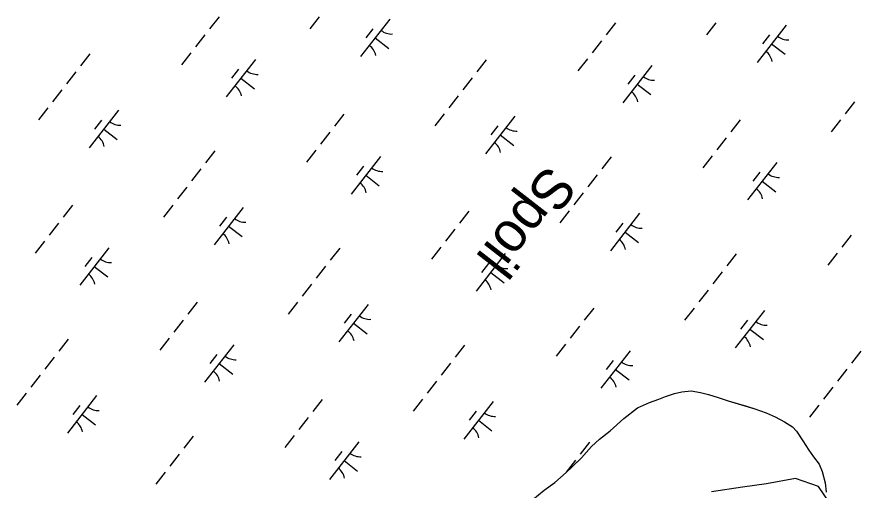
# Model space of a CAD drawing. Extents: x 3888273 to 3909528, y 158682 to 181032.
# Drawn here: x 3900589 to 3901471, y 173553 to 174052 of the extents above; entities that cross this region are included whole.
import ezdxf

# ---------------------------------------------------------------- set-up
doc = ezdxf.new("R2010")
doc.units = 0
for name, color, linetype in [('V-CHAN-SPOL', 7, 'Continuous'), ('V-RIVR-EDGE', 7, 'Continuous'), ('V-TOPO-SHOR', 7, 'Continuous'), ('V-WETL-SWMP', 7, 'Continuous')]:
    doc.layers.add(name, color=color, linetype=linetype)

msp = doc.modelspace()

# ---------------------------------------------------------------- linework, layer by layer
at = {"layer": 'V-RIVR-EDGE'}
msp.add_lwpolyline([(3901444.18, 173539.89), (3901432.1, 173557.55), (3901407.94, 173565.91), (3901377.27, 173560.34), (3901352.18, 173556.62), (3901319.66, 173551.97)], dxfattribs=at)
at = {"layer": 'V-TOPO-SHOR'}
for points in [[(3901131.66, 173543.88), (3901143.9, 173553.57), (3901154.97, 173561.65), (3901166.81, 173572.13), (3901173.11, 173578.17), (3901182.97, 173587.43), (3901193.6, 173599.49), (3901201.89, 173607.14), (3901212.94, 173616.02), (3901227.54, 173628.92), (3901241.76, 173640.22), (3901254.45, 173645.93), (3901264.37, 173649.22), (3901271.11, 173652.08), (3901280.64, 173655.37)], [(3901280.64, 173655.37), (3901288.58, 173657.04), (3901298.14, 173657.94), (3901308.11, 173656.45), (3901316.5, 173654.15), (3901326.48, 173651.07), (3901337.27, 173647.6), (3901356.45, 173641.83), (3901365.24, 173639.13), (3901377.24, 173634.87), (3901386.44, 173630.59), (3901396.45, 173625.52), (3901404.87, 173620.03), (3901408.9, 173615.69), (3901415.78, 173605.4), (3901421.86, 173595.51), (3901426.71, 173588.79), (3901432.76, 173580.89), (3901436.03, 173573.36), (3901438.94, 173561.44), (3901440.24, 173551.5)]]:
    msp.add_lwpolyline(points, dxfattribs=at)
at = {"layer": 'V-WETL-SWMP'}
for p, q in [((3900801.93, 174051.41), (3900792.1, 174038.79)), ((3900907.39, 174051.66), (3900897.57, 174039.03)), ((3900981.53, 174049.18), (3900950.83, 174009.72)), ((3901218.59, 174045.19), (3901208.77, 174032.56)), ((3901324.06, 174045.43), (3901314.23, 174032.8)), ((3901398.2, 174042.96), (3901367.5, 174003.5)), ((3900787.19, 174032.47), (3900777.36, 174019.84)), ((3900963.78, 174038.93), (3900956.41, 174029.45)), ((3901380.44, 174032.7), (3901373.07, 174023.23)), ((3900966.18, 174029.45), (3900980.39, 174018.4)), ((3901203.86, 174026.25), (3901194.03, 174013.62)), ((3901382.85, 174023.23), (3901397.06, 174012.17)), ((3900666.22, 174012.56), (3900656.39, 173999.94)), ((3900772.45, 174013.53), (3900762.63, 174000.9)), ((3900840.29, 174006.73), (3900809.59, 173967.27)), ((3901082.88, 174006.34), (3901073.06, 173993.71)), ((3901189.12, 174007.3), (3901179.29, 173994.68)), ((3900822.54, 173996.48), (3900815.17, 173987.01)), ((3901256.96, 174000.51), (3901226.26, 173961.05)), ((3900651.48, 173993.62), (3900641.65, 173980.99)), ((3901239.2, 173990.25), (3901231.83, 173980.78)), ((3900824.94, 173987), (3900839.15, 173975.95)), ((3901068.15, 173987.4), (3901058.32, 173974.77)), ((3901241.61, 173980.78), (3901255.81, 173969.72)), ((3900636.74, 173974.68), (3900626.92, 173962.05)), ((3901053.41, 173968.45), (3901043.58, 173955.83)), ((3901470.08, 173962.23), (3901460.25, 173949.6)), ((3900622, 173955.74), (3900612.18, 173943.11)), ((3900696.15, 173953.26), (3900665.44, 173913.8)), ((3900933.21, 173949.27), (3900923.38, 173936.64)), ((3901038.67, 173949.51), (3901028.85, 173936.88)), ((3901112.81, 173947.04), (3901082.11, 173907.58)), ((3900678.39, 173943.01), (3900671.02, 173933.54)), ((3901095.06, 173936.78), (3901087.69, 173927.31)), ((3901349.88, 173943.04), (3901340.05, 173930.42)), ((3901455.34, 173943.29), (3901445.51, 173930.66)), ((3900680.79, 173933.53), (3900695, 173922.48)), ((3900918.47, 173930.33), (3900908.64, 173917.7)), ((3901097.46, 173927.31), (3901111.67, 173916.25)), ((3901335.14, 173924.1), (3901325.31, 173911.47)), ((3900797.5, 173910.42), (3900787.67, 173897.79)), ((3900903.73, 173911.39), (3900893.91, 173898.76)), ((3900971.57, 173904.59), (3900940.87, 173865.13)), ((3901214.17, 173904.19), (3901204.34, 173891.56)), ((3901320.4, 173905.16), (3901310.57, 173892.53)), ((3900782.76, 173891.48), (3900772.93, 173878.85)), ((3900953.82, 173894.33), (3900946.45, 173884.86)), ((3901388.24, 173898.36), (3901357.54, 173858.9)), ((3900956.22, 173884.86), (3900970.43, 173873.81)), ((3901199.43, 173885.25), (3901189.6, 173872.62)), ((3901370.48, 173888.11), (3901363.11, 173878.64)), ((3901372.89, 173878.63), (3901387.09, 173867.58)), ((3900768.02, 173872.53), (3900758.2, 173859.91)), ((3901184.69, 173866.31), (3901174.86, 173853.68)), ((3900647.82, 173853.35), (3900638, 173840.72)), ((3900753.28, 173853.59), (3900743.46, 173840.96)), ((3900827.43, 173851.12), (3900796.72, 173811.66)), ((3901064.49, 173847.12), (3901054.66, 173834.5)), ((3901169.95, 173847.37), (3901160.13, 173834.74)), ((3900809.67, 173840.86), (3900802.3, 173831.39)), ((3901244.09, 173844.89), (3901213.39, 173805.43)), ((3900633.08, 173834.41), (3900623.26, 173821.78)), ((3900812.08, 173831.39), (3900826.28, 173820.34)), ((3901226.34, 173834.64), (3901218.97, 173825.17)), ((3901049.75, 173828.18), (3901039.93, 173815.55)), ((3901228.74, 173825.16), (3901242.95, 173814.11)), ((3901466.42, 173821.96), (3901456.59, 173809.33)), ((3900618.35, 173815.47), (3900608.52, 173802.84)), ((3900686.19, 173808.67), (3900655.48, 173769.21)), ((3900928.78, 173808.27), (3900918.95, 173795.65)), ((3901035.01, 173809.24), (3901025.19, 173796.61)), ((3901102.85, 173802.45), (3901072.15, 173762.98)), ((3901451.68, 173803.02), (3901441.86, 173790.39)), ((3900668.43, 173798.41), (3900661.06, 173788.94)), ((3901345.45, 173802.05), (3901335.62, 173789.42)), ((3900670.83, 173788.94), (3900685.04, 173777.89)), ((3900914.04, 173789.33), (3900904.22, 173776.7)), ((3901085.1, 173792.19), (3901077.73, 173782.72)), ((3901087.5, 173782.71), (3901101.71, 173771.66)), ((3901330.71, 173783.11), (3901320.88, 173770.48)), ((3900899.3, 173770.39), (3900889.48, 173757.76)), ((3901315.97, 173764.16), (3901306.14, 173751.54)), ((3900779.1, 173751.21), (3900769.28, 173738.58)), ((3900884.56, 173751.45), (3900874.74, 173738.82)), ((3900958.71, 173748.98), (3900928, 173709.51)), ((3901195.77, 173744.98), (3901185.94, 173732.35)), ((3901301.23, 173745.22), (3901291.41, 173732.59)), ((3901375.38, 173742.75), (3901344.67, 173703.29)), ((3900764.36, 173732.26), (3900754.54, 173719.64)), ((3900940.95, 173738.72), (3900933.58, 173729.25)), ((3901357.62, 173732.49), (3901350.25, 173723.02)), ((3900943.36, 173729.24), (3900957.56, 173718.19)), ((3901181.03, 173726.04), (3901171.21, 173713.41)), ((3901360.02, 173723.02), (3901374.23, 173711.96)), ((3900643.39, 173712.35), (3900633.57, 173699.73)), ((3900749.63, 173713.32), (3900739.8, 173700.69)), ((3900817.47, 173706.53), (3900786.76, 173667.06)), ((3901060.06, 173706.13), (3901050.23, 173693.5)), ((3901166.29, 173707.1), (3901156.47, 173694.47)), ((3901234.13, 173700.3), (3901203.43, 173660.84)), ((3901476.73, 173699.9), (3901466.9, 173687.28)), ((3900628.65, 173693.41), (3900618.83, 173680.78)), ((3900799.71, 173696.27), (3900792.34, 173686.8)), ((3901216.38, 173690.04), (3901209.01, 173680.57)), ((3900802.11, 173686.8), (3900816.32, 173675.74)), ((3901045.32, 173687.19), (3901035.5, 173674.56)), ((3901218.78, 173680.57), (3901232.99, 173669.52)), ((3901461.99, 173680.96), (3901452.16, 173668.33)), ((3900613.92, 173674.47), (3900604.09, 173661.84)), ((3901030.58, 173668.25), (3901020.76, 173655.62)), ((3901447.25, 173662.02), (3901437.43, 173649.39)), ((3900599.18, 173655.53), (3900589.35, 173642.9)), ((3900673.32, 173653.06), (3900642.62, 173613.59)), ((3901271.11, 173652.08), (3901280.64, 173655.37)), ((3901280.64, 173655.37), (3901288.58, 173657.04)), ((3901288.58, 173657.04), (3901298.13, 173657.94)), ((3901298.13, 173657.94), (3901308.11, 173656.45)), ((3901308.11, 173656.45), (3901316.5, 173654.15)), ((3901316.5, 173654.15), (3901326.48, 173651.07)), ((3900910.38, 173649.06), (3900900.56, 173636.43)), ((3901015.85, 173649.3), (3901006.02, 173636.68)), ((3901089.99, 173646.83), (3901059.28, 173607.37)), ((3901241.76, 173640.22), (3901254.45, 173645.93)), ((3901254.45, 173645.93), (3901264.37, 173649.22)), ((3901264.37, 173649.22), (3901271.11, 173652.08)), ((3901326.48, 173651.07), (3901337.27, 173647.6)), ((3901337.27, 173647.6), (3901365.24, 173639.13)), ((3900655.56, 173642.8), (3900648.2, 173633.33)), ((3901072.23, 173636.57), (3901064.86, 173627.1)), ((3901227.54, 173628.92), (3901241.76, 173640.22)), ((3901365.24, 173639.13), (3901377.24, 173634.87)), ((3901432.51, 173643.08), (3901422.69, 173630.45)), ((3900657.97, 173633.33), (3900672.18, 173622.27)), ((3900895.64, 173630.12), (3900885.82, 173617.49)), ((3901074.64, 173627.1), (3901088.84, 173616.05)), ((3901212.94, 173616.02), (3901227.54, 173628.92)), ((3901377.24, 173634.87), (3901386.44, 173630.59)), ((3901386.44, 173630.59), (3901396.45, 173625.52)), ((3901396.45, 173625.52), (3901404.87, 173620.03)), ((3901404.87, 173620.03), (3901408.9, 173615.69)), ((3900774.67, 173610.21), (3900764.85, 173597.58)), ((3900880.91, 173611.18), (3900871.08, 173598.55)), ((3901201.89, 173607.14), (3901212.94, 173616.02)), ((3901408.9, 173615.69), (3901415.78, 173605.41)), ((3900948.75, 173604.38), (3900918.04, 173564.92)), ((3901191.34, 173603.98), (3901181.51, 173591.36)), ((3901193.6, 173599.49), (3901201.89, 173607.14)), ((3901415.78, 173605.41), (3901421.86, 173595.51)), ((3900759.93, 173591.27), (3900750.11, 173578.64)), ((3900930.99, 173594.12), (3900923.62, 173584.65)), ((3901182.97, 173587.43), (3901193.6, 173599.49)), ((3901421.86, 173595.51), (3901426.71, 173588.79)), ((3900933.4, 173584.65), (3900947.6, 173573.6)), ((3901176.6, 173585.04), (3901166.78, 173572.41)), ((3901166.81, 173572.13), (3901182.97, 173587.43)), ((3901426.71, 173588.79), (3901432.77, 173580.89)), ((3901432.77, 173580.89), (3901436.03, 173573.36)), ((3901436.03, 173573.36), (3901438.94, 173561.44)), ((3900745.2, 173572.33), (3900735.37, 173559.7)), ((3901154.97, 173561.65), (3901166.81, 173572.13)), ((3901143.9, 173553.57), (3901154.97, 173561.65)), ((3901438.94, 173561.44), (3901440.24, 173551.5)), ((3901131.66, 173543.88), (3901143.9, 173553.57))]:
    msp.add_line(p, q, dxfattribs=at)
for centre, start, end in [((3900983.33, 174051.11), 231.34298, 272.88664), ((3901400, 174044.88), 231.34298, 272.88664), ((3900949.41, 174007.51), 11.34298, 52.88663), ((3901366.07, 174001.28), 11.34298, 52.88663), ((3900842.09, 174008.66), 231.34298, 272.88664), ((3901258.76, 174002.43), 231.34298, 272.88664), ((3900808.17, 173965.06), 11.34298, 52.88663), ((3901224.83, 173958.83), 11.34298, 52.88663), ((3900697.94, 173955.19), 231.34298, 272.88664), ((3901114.61, 173948.96), 231.34298, 272.88664), ((3900664.02, 173911.59), 11.34298, 52.88663), ((3901080.69, 173905.36), 11.34298, 52.88663), ((3900973.37, 173906.51), 231.34298, 272.88664), ((3901390.04, 173900.29), 231.34298, 272.88664), ((3900939.45, 173862.91), 11.34298, 52.88663), ((3901356.11, 173856.69), 11.34298, 52.88663), ((3900829.22, 173853.04), 231.34298, 272.88664), ((3901245.89, 173846.82), 231.34298, 272.88664), ((3900795.3, 173809.44), 11.34298, 52.88663), ((3901211.97, 173803.22), 11.34298, 52.88663), ((3900687.98, 173810.59), 231.34298, 272.88664), ((3901104.65, 173804.37), 231.34298, 272.88664), ((3900654.06, 173766.99), 11.34298, 52.88663), ((3901070.73, 173760.77), 11.34298, 52.88663), ((3900960.5, 173750.9), 231.34298, 272.88664), ((3901377.17, 173744.67), 231.34298, 272.88664), ((3900926.58, 173707.3), 11.34298, 52.88663), ((3901343.25, 173701.07), 11.34298, 52.88663), ((3900819.26, 173708.45), 231.34298, 272.88664), ((3901235.93, 173702.22), 231.34298, 272.88664), ((3900785.34, 173664.85), 11.34298, 52.88663), ((3901202.01, 173658.62), 11.34298, 52.88663), ((3900675.12, 173654.98), 231.34298, 272.88664), ((3901091.79, 173648.75), 231.34298, 272.88664), ((3900641.19, 173611.38), 11.34298, 52.88663), ((3901057.86, 173605.15), 11.34298, 52.88663), ((3900950.54, 173606.3), 231.34298, 272.88664), ((3900916.62, 173562.7), 11.34298, 52.88663)]:
    msp.add_arc(centre, 17.62, start, end, dxfattribs=at)

# ---------------------------------------------------------------- texts
at = {"layer": 'V-CHAN-SPOL'}
msp.add_text('Spoil', height=42, rotation=232.11852, dxfattribs=at).set_placement((3901147.29, 173897.55))

doc.saveas('drawing.dxf')
